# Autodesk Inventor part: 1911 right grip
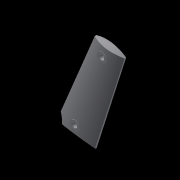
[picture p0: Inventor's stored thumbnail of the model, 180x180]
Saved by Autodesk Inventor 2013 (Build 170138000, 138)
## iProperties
Created: 2012-12
Part Number: 1911 right grip
Material: Generic
Document SubType Name: Modeling
Designer: John
Density: 1 g/cm^3
Author: John
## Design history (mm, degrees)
sketch "Sketch1"
  geometry: L1 (-53.04, -101.07)-(-35.834, -46.497) reference; L2 (-10.008, -33.299)-(0.762, -33.299); L3 (0.762, -9.83)-(-10.008, -9.83); L4 (0.762, -36.551)-(-22.268, -36.551) reference; L5 (15.748, -21.565)-(15.748, -19.304); L6 (67.564, -8.128)-(26.924, -8.128); L7 (-76.708, -32.918)-(-101.947, -93.849) reference; L8 (-101.947, -93.849)-(-53.04, -101.07) reference; L9 (67.564, -8.128)-(67.564, 5.867) reference; L10 (67.564, 5.867)-(9.144, 5.867) reference; L11 (9.144, 5.867)-(9.144, 11.43) reference; L12 (-81.119, 7.237)-(-80.862, 11.43); L13 (9.144, 11.43)-(-80.862, 11.43); L14 (-87.018, -8.028)-(-94.136, -5.079) reference; C1 r 2.553 at (0, 0) reference; C2 r 1.994 at (-95.123, -91.313) reference; C3 r 2 at (-75.514, 0.406) reference; C4 r 1.905 at (-85.547, -5.334) reference; C5 r 3.175 at (-30.302, -27.813); A1 r 11.735 centre (0.762, -21.565) between (0.762, -33.299) and (0.762, -9.83) reference; A2 r 14.986 centre (0.762, -21.565) between (0.762, -36.551) and (15.748, -21.565) reference; A3 r 11.735 centre (-10.008, -21.565) between (-10.008, -9.83) and (-10.008, -33.299) reference; A4 r 14.224 centre (-22.268, -50.775) between (-22.268, -36.551) and (-35.834, -46.497) reference; A5 r 11.176 centre (26.924, -19.304) between (26.924, -8.128) and (15.748, -19.304) reference; A6 r 8.763 centre (-89.865, 7.772) between (-88.554, -0.892) and (-81.119, 7.237) reference; A7 r 7.366 centre (-87.452, -8.175) between (-88.554, -0.892) and (-94.136, -5.079); A8 r 19.05 centre (-94.308, -25.628) between (-76.708, -32.918) and (-87.018, -8.028) reference; 3 further points
  constraints: 28 end point, 17 point on circle, 13 centre point, 13 tangent, 5 perpendicular, 2 coincident, 2 horizontal, 2 vertical, 1 midpoint, 1 parallel, 18 other
  dimensions: "d145" = 6.35 diameter of C5
extrude "Extrusion2" new body sketch "Sketch1" stored distance "d59" = 19.3548; taper "d60" = 0 deg
sketch "3D Sketch2"
sweep "Sweep2" sketch "3D Sketch2" dims "d62" = 0
sketch "Sketch4"
  geometry: L1 (-76.073, -16.93)-(-84.092, -1.85) reference; L2 (-74.409, -30.482)-(-81.214, -57.775) reference; L3 (-92.893, -13.174)-(-101.295, -13.174) reference; L4 (-77.94, -44.643)-(-90.574, -45.416); L5 (-90.574, -45.416)-(-82.294, -32.869); C1 r 1.905 at (-85.547, -5.334) reference; A1 r 19.05 centre (-92.893, -25.874) between (-74.409, -30.482) and (-76.073, -16.93) reference; A2 r 12.7 centre (-92.893, -25.874) between (-89.029, -13.776) and (-92.893, -13.174) reference; A3 r 35.814 centre (-88.437, -37.399) between (-84.092, -1.85) and (-98.411, -3.002) reference; A4 r 2.794 centre (-101.295, -10.38) between (-104.089, -10.38) and (-101.295, -13.174) reference; A5 r 2.794 centre (-101.295, -10.38) between (-104.087, -10.278) and (-101.295, -13.174); A6 r 7.874 centre (-96.219, -10.564) between (-98.411, -3.002) and (-104.087, -10.278) reference; A7 r 12.7 centre (-92.893, -25.874) between (-89.029, -13.776) and (-92.893, -13.174); A8 r 12.7 centre (-92.893, -25.874) between (-82.294, -32.869) and (-92.893, -13.174); 2 further points
  constraints: 18 point on circle, 10 end point, 9 centre point, 4 coincident, 2 concentric, 1 horizontal, 1 point on line, 1 tangent, 8 other
extrude "Extrusion3" join sketch "Sketch4" stored distance "d97" = 15.7226; taper "d98" = 0 deg
workplane "Work Plane1"
sketch "Sketch5"
  geometry: L1 (-7.861, 0)-(7.861, 0) reference; L2 (7.861, -12.018)-(7.861, 0) reference; L3 (-7.861, -12.018)-(7.861, -12.018) reference; L4 (-7.861, 0)-(-7.861, -12.018) reference; L5 (-3.937, 0)-(3.937, 0); L6 (-7.861, -12.018)-(-1.003, -12.018); L7 (0, 0)-(0, -8.629); A1 r 6.858 centre (-1.003, -6.199) between (-3.937, 0) and (-7.861, -6.199); A2 r 6.858 centre (1.003, -6.199) between (7.861, -6.199) and (3.937, 0); 1 further point
  constraints: 6 end point, 5 point on line, 4 point on circle, 2 centre point, 2 symmetric about line, 1 midpoint, 1 perpendicular, 2 other
extrude "Extrusion4" cut sketch "Sketch5" stored distance "d106" = 15.7226; taper "d107" = 0 deg
sketch "Sketch6"
  geometry: L1 (92.893, -13.174)-(101.295, -13.174) reference; L2 (94.719, -6.486)-(94.136, -5.079) reference; L3 (87.601, -9.435)-(94.719, -6.486) reference; L4 (101.295, -13.174)-(81.975, -13.174); A1 r 2.794 centre (101.295, -10.38) between (101.295, -13.174) and (104.087, -10.278) reference; A2 r 7.874 centre (96.219, -10.564) between (104.087, -10.278) and (98.411, -3.002) reference; A3 r 35.814 centre (88.437, -37.399) between (98.411, -3.002) and (90.909, -1.67) reference; A4 r 7.366 centre (87.452, -8.175) between (94.136, -5.079) and (90.909, -1.67) reference; 2 further points
  constraints: 2 end point, 1 collinear, 1 tangent, 2 other
extrude "Extrusion5" cut sketch "Sketch6" distance "d108" = 3.937; taper "d109" = 0 deg
mirror "Mirror1"
workplane "Work Plane2"
sweep "Sweep3" dims "d115" = 0
sweep "Sweep4" dims "d119" = 0
workplane "Work Plane3"
sweep "Sweep6" dims "d131" = 0
sketch "Sketch15"
  geometry: L1 (-20.851, -26.05)-(-20.851, -26.76) reference; L2 (-21.738, -21.901)-(-21.738, -26.76) reference; L3 (-25.508, -35.793)-(-26.989, -39.681); L4 (-26.989, -39.681)-(21.805, -39.681); L5 (21.805, -39.681)-(21.805, -10.457); L6 (21.805, -10.457)-(-11.471, -10.457); L7 (-11.471, -10.457)-(-21.738, -21.901); A1 r 15.328 centre (-22.268, -50.775) between (-24.079, -35.554) and (-25.508, -35.793) reference; A2 r 13.591 centre (-34.442, -26.76) between (-24.079, -35.554) and (-20.851, -26.76) reference; A3 r 11.735 centre (-10.008, -21.565) between (-21.738, -21.901) and (-20.851, -26.05) reference; A4 r 12.705 centre (-34.442, -26.76) between (-25.508, -35.793) and (-21.738, -26.76) reference; 1 further point
  constraints: 10 end point, 3 perpendicular
extrude "Extrusion6" cut sketch "Sketch15" stored distance "d132" = 37.338; taper "d133" = 0 deg
mirror "Mirror2"
workplane "Work Plane6"
sketch "Sketch21"
  geometry: L1 (0, 0)-(19.355, 0) reference; L2 (1.321, -3.607)-(1.321, 0); L3 (18.034, -3.607)-(18.034, 0); A1 r 10.389 centre (9.677, -3.607) between (0, -7.384) and (19.355, -7.384) reference; A2 r 8.357 centre (9.677, -3.607) between (1.321, -3.607) and (18.034, -3.607); 1 further point
  constraints: 4 end point, 2 point on circle, 2 point on line, 2 tangent, 1 centre point, 1 coincident, 1 parallel, 1 perpendicular
  dimensions: "d151" = 16.7132 diameter of A2
extrude "Extrusion7" cut sketch "Sketch21" stored distance "d152" = 37.338; taper "d153" = 0 deg
sketch "Sketch22"
  geometry: L1 (0, 5.563)-(19.355, 5.563) reference; L2 (0, 0)-(1.321, 0) reference; L3 (1.702, 0)-(1.702, 3.023); L4 (0, 3.023)-(1.702, 3.023); L5 (1.702, 0)-(0, 0); L6 (9.677, -3.607)-(9.677, 2.087); L7 (19.355, 3.023)-(17.653, 3.023); L8 (17.653, 0)-(17.653, 3.023); L9 (17.653, 0)-(19.355, 0); L10 (0, 3.023)-(0, 0); L11 (19.355, 3.023)-(19.355, 0); A1 r 8.357 centre (9.677, -3.607) between (1.321, -3.607) and (18.034, -3.607) reference; 1 further point
  constraints: 18 end point, 4 perpendicular, 3 symmetric about line, 1 collinear, 1 parallel
  dimensions: "d155" = 2.54 distance of L1.start L4.start
extrude "Extrusion8" cut sketch "Sketch22" stored distance "d156" = 37.338; taper "d157" = 0 deg
sweep "Sweep7" dims "d159" = 0
sketch "Sketch26"
  geometry: L1 (-94.719, -6.486)-(-94.136, -5.079); L2 (-87.601, -9.435)-(-94.719, -6.486); L3 (-87.601, -9.435)-(-94.579, -6.544) reference; L4 (-89.65, -13.174)-(-81.975, -13.174) reference; L5 (-92.893, -12.766)-(-102.748, -12.766) reference; L6 (-94.371, -4.976)-(-96.086, -9.116) reference; L7 (-96.086, -9.116)-(-95.709, -9.272) reference; L8 (-104.087, -10.278)-(-87.601, -9.435); A1 r 7.874 centre (-96.219, -10.564) between (-98.411, -3.002) and (-104.087, -10.278); A2 r 35.814 centre (-88.437, -37.399) between (-90.909, -1.67) and (-98.411, -3.002); A3 r 7.366 centre (-87.452, -8.175) between (-90.909, -1.67) and (-94.136, -5.079); A4 r 13.108 centre (-92.893, -25.874) between (-89.65, -13.174) and (-92.893, -12.766) reference; A5 r 2.794 centre (-101.295, -10.38) between (-104.087, -10.278) and (-102.748, -12.766) reference; A6 r 7.874 centre (-96.219, -10.564) between (-98.411, -3.002) and (-104.087, -10.278) reference; A7 r 35.814 centre (-88.437, -37.399) between (-91.5, -1.716) and (-98.411, -3.002) reference; A8 r 7.622 centre (-87.452, -8.175) between (-91.5, -1.716) and (-94.371, -4.976) reference; 1 further point
  constraints: 6 end point, 6 point on circle, 3 centre point, 2 other
extrude "Extrusion9" join sketch "Sketch26" stored distance "d160" = 7.8486; taper "d161" = 0 deg
sketch "Sketch27"
  geometry: L1 (0, 0)-(-41.219, -130.729); L2 (0, 0)-(137.073, 0); L3 (-55.804, 11.43)-(-98.449, -123.824); L4 (-79.932, 11.43)-(9.144, 11.43) reference; L5 (-89.574, -95.676)-(-61.783, -99.779); L6 (-61.783, -99.779)-(-26.719, 11.43); C1 r 1.994 at (-95.123, -91.313) reference
  constraints: 10 end point, 3 point on line, 1 equal length, 1 horizontal, 1 parallel
  dimensions: "d162" = 107.5 deg angle of L1 L2; "d165" = 28.0924 distance of L5.start L5.end
extrude "Extrusion10" cut sketch "Sketch27" stored distance "d166" = 13.9954; taper "d167" = 0 deg
workplane "Work Plane7"
sketch "Sketch28"
  geometry: C1 r 6.998 at (0, 0); 1 further point
  constraints: 1 centre point
  dimensions: "d169" = 13.9954 diameter of C1
extrude "Extrusion11" cut sketch "Sketch28" stored distance "d170" = 22.5171; taper "d171" = 0 deg
workplane "Work Plane8"
sketch "Sketch30"
  geometry: L1 (-10.008, -9.83)-(0.762, -9.83) reference; L2 (0.762, -33.299)-(-10.008, -33.299) reference; A1 r 11.735 centre (-10.008, -21.565) between (-10.008, -9.83) and (-21.742, -21.565) reference; A2 r 11.735 centre (0.762, -21.565) between (0.762, -33.299) and (1.099, -9.835) reference; A3 r 11.735 centre (-10.008, -21.565) between (-21.738, -21.901) and (-10.008, -33.299) reference; 1 further point
  constraints: 2 other
sweep "Sweep8" sketch "Sketch30" dims "d173" = 0
sketch "Sketch31"
  geometry: L1 (31.241, 6.452)-(41.564, 6.452); L2 (31.241, 6.452)-(31.241, -6.452); L3 (31.241, -6.452)-(41.564, -6.452); L4 (41.564, -6.452)-(41.564, 6.452); 7 further points; 2 other entities
  constraints: 8 end point, 2 horizontal, 1 perpendicular, 1 vertical, 2 other
  dimensions: "d174" = 6.4516 distance of point (31.241, 0) L1.start; "d175" = 12.9032 distance of L1.start L2.end
extrude "Extrusion12" cut sketch "Sketch31" distance "d176" = 2.159; taper "d177" = 0 deg
sketch "Sketch32"
  geometry: C1 r 2.54 at (-76.657, -84.049); C2 r 2.54 at (-49.2, -10.947)
  constraints: 2 centre point
  dimensions: "d180" = 5.08 diameter of C1; "d185" = 5.08 diameter of C2
extrude "Extrusion13" cut sketch "Sketch32" stored distance "d181" = 2.159; taper "d182" = 0 deg
sketch "Sketch33"
  geometry: L1 (-55.804, 11.43)-(-89.574, -95.676) reference; L2 (-82.294, -32.869)-(-90.574, -45.416) reference; L3 (-85.446, -45.102)-(-90.059, -45.384) reference; L4 (-90.574, -45.416)-(-90.059, -45.384) reference; L5 (-89.328, -43.527)-(-86.814, -45.186); 1 further point
  constraints: 2 end point, 2 point on line, 1 perpendicular
extrude "Extrusion14" cut sketch "Sketch33" distance "d186" = 25.4; taper "d187" = 0 deg
sketch "Sketch34"
  geometry: L1 (59.664, -100.092)-(101.947, -93.849) reference; L2 (92.046, -94.569)-(60.876, -99.275) reference; L3 (31.159, -5.307)-(60.937, -99.266) reference; L4 (61.169, -0.636)-(95.891, -84.128); C1 r 2.54 at (76.657, -84.049) reference; C2 r 2.54 at (49.2, -10.947) reference; A1 r 8.636 centre (100.167, -91.631) between (95.891, -84.128) and (92.334, -95.268); A2 r 34.544 centre (50.936, -33.629) between (61.169, -0.636) and (31.159, -5.307)
  constraints: 6 end point, 5 point on circle, 2 centre point, 2 point on line, 3 other
extrude "Extrusion15" join sketch "Sketch34" distance "d209" = 6.477; taper "d210" = 0 deg
workplane "Work Plane9"
workplane "Work Plane12"
workplane "Work Plane13"
loft "Loft1" dims "d219" = 0, "d220" = 90 deg, "d221" = 0, "d222" = 90 deg
workplane "Work Plane14"
sketch "Sketch39"
  geometry: L1 (0, 0)-(1.524, 0) reference; L2 (1.524, 0)-(9.15, -7.626); L3 (1.524, 0)-(12.309, 0); L4 (9.15, -7.626)-(9.15, 0); L5 (9.15, 0)-(1.524, 0); 1 further point
  constraints: 8 end point, 2 perpendicular, 1 equal length, 1 horizontal, 1 point on line
  dimensions: "d224" = 45 deg angle of L2 L3
extrude "Extrusion16" cut sketch "Sketch39" distance "d225" = 44.82993; taper "d226" = 0 deg
sketch "3D Sketch3"
sweep "Sweep9" sketch "3D Sketch3" dims "d228" = 0
mirror "Mirror3"
mirror "Mirror4"
sketch "Sketch41"
  geometry: L1 (-10.008, -32.408)-(0.762, -32.408) reference; L2 (-10.008, -10.721)-(0.762, -10.721) reference; L3 (-10.008, -10.721)-(-17.523, -10.721); L4 (-10.008, -32.408)-(-17.523, -32.408); A1 r 12.7 centre (-2.998, -21.565) between (-9.608, -10.721) and (-9.608, -32.408); A2 r 13.193 centre (-10.008, -21.565) between (-17.523, -10.721) and (-17.523, -32.408); 2 further points
  constraints: 4 end point, 4 point on circle, 2 centre point, 2 point on line, 1 coincident, 1 collinear, 1 parallel
extrude "Extrusion17" join sketch "Sketch41" stored distance "d230" = 5.7404; taper "d231" = 0 deg
sketch "Sketch43"
  geometry: A1 r 12.7 centre (-2.998, -21.565) between (-9.608, -10.721) and (-9.608, -32.408) reference; 1 further point
sweep "Sweep10" sketch "Sketch43" dims "d233" = 0
sketch "Sketch44"
  geometry: L1 (9.144, 8.89)-(9.144, 11.43) reference; L2 (9.144, 11.43)-(-79.932, 11.43) reference; L3 (9.144, 11.43)-(9.144, 11.176); L4 (9.144, 11.176)-(-89.177, 11.176); L5 (-89.177, 11.176)-(-89.177, 11.43); L6 (-89.177, 11.43)-(-79.932, 11.43); 1 further point
  constraints: 8 end point, 2 parallel, 2 point on line, 1 perpendicular
  dimensions: "d234" = 0.254 distance of L1.end L3.end
extrude "Extrusion18" cut sketch "Sketch44" stored distance "d235" = 5.7404; taper "d236" = 0 deg
sketch "Sketch45"
  geometry: L1 (18.034, 8.915)-(-1.321, 8.915) reference; L2 (-1.321, 6.629)-(-1.321, 8.915) reference; L3 (-1.321, 6.629)-(0.381, 6.629) reference; L4 (16.332, 6.629)-(18.034, 6.629) reference; L5 (18.034, 8.915)-(18.034, 6.629) reference; L6 (18.034, 6.629)-(17.78, 6.629); L7 (17.78, 6.629)-(17.78, 8.915); L8 (-1.321, 6.629)-(-1.067, 6.629); L9 (-1.067, 6.629)-(-1.067, 8.915); 1 further point
  constraints: 8 end point, 4 point on line, 2 perpendicular
  dimensions: "d237" = 0.254 distance of L4.end L6.end; "d238" = 0.254 distance of L2.start L8.end
extrude "Extrusion19" cut sketch "Sketch45" stored distance "d239" = 25.4; taper "d240" = 0 deg
sketch "Sketch47"
  geometry: L1 (-84.404, 0.406)-(-84.404, 18.681); L2 (-84.404, 18.681)-(-73.514, 18.681); L3 (-73.514, 9.068)-(-73.514, 18.681); C1 r 2 at (-75.514, 0.406) reference; A1 r 8.89 centre (-75.514, 0.406) between (-84.404, 0.406) and (-66.624, 0.406); A2 r 8.89 centre (-75.514, 0.406) between (-84.404, 0.406) and (-73.514, 9.068); 1 further point
  constraints: 6 end point, 5 point on circle, 2 centre point, 2 coincident, 2 perpendicular, 2 tangent, 1 vertical
extrude "Extrusion21" cut sketch "Sketch47" stored distance "d245" = 8.001; taper "d246" = 0 deg
sketch "Sketch51"
  geometry: C1 r 2.54 at (49.2, -10.947) reference; C2 r 2.54 at (76.657, -84.049) reference; C3 r 4.826 at (49.2, -10.947); C4 r 4.826 at (76.657, -84.049); 1 further point
  constraints: 2 centre point, 2 coincident
  dimensions: "d251" = 9.652 diameter of C3; "d252" = 9.652 diameter of C4
extrude "Extrusion22" join sketch "Sketch51" distance "d253" = 9.398; taper "d254" = 0 deg
mirror "Mirror5"
sketch "Sketch52"
  geometry: L1 (17.78, 8.915)-(-1.067, 8.915) reference; L2 (12.992, 3.321)-(12.992, 8.915); L3 (3.721, 3.321)-(3.721, 8.915); L4 (3.721, 8.915)-(12.992, 8.915); A1 r 8.357 centre (8.357, 0) between (0, 0) and (16.713, 0) reference; A2 r 5.702 centre (8.357, 0) between (3.721, 3.321) and (12.992, 3.321); 1 further point
  constraints: 6 end point, 2 point on circle, 2 point on line, 1 centre point, 1 coincident, 1 collinear, 1 perpendicular
extrude "Extrusion23" cut sketch "Sketch52" distance "d258" = 20.1168; taper "d259" = 0 deg
sketch "Sketch53"
  geometry: L1 (10.3, -7.696)-(10.3, -5.361); L2 (10.3, -7.696)-(6.414, -7.696); L3 (6.414, -7.696)-(6.414, -5.361); A1 r 5.702 centre (8.357, 0) between (3.721, 3.321) and (12.992, 3.321) reference; 1 further point
  constraints: 6 end point, 2 perpendicular, 2 point on circle
extrude "Extrusion24" cut sketch "Sketch53" distance "d263" = 13.7668; taper "d264" = 0 deg
sketch "Sketch54"
  geometry: L1 (12.992, 8.915)-(12.992, 3.321) reference; L2 (3.721, 8.915)-(12.992, 8.915); A1 r 8.839 centre (8.357, 16.442) between (3.721, 8.915) and (12.992, 8.915); 1 further point
  constraints: 2 end point, 2 point on circle, 1 centre point, 1 perpendicular
extrude "Extrusion25" cut sketch "Sketch54" distance "d266" = 34.925; taper "d267" = 0 deg
sketch "Sketch55"
  geometry: L1 (67.564, 5.867)-(-80.363, 5.867) reference; L2 (-20.469, -6.245)-(-10.008, -6.245); L3 (-20.469, -24.235)-(0, -24.235); A1 r 15.32 centre (-10.008, -21.565) between (-10.008, -6.245) and (-25.327, -21.565) reference; A2 r 8.995 centre (-20.469, -15.24) between (-20.469, -6.245) and (-20.469, -24.235) reference
  constraints: 4 end point, 3 tangent, 2 parallel, 2 point on circle, 1 centre point, 2 other
workplane "Work Plane17"
sketch "Sketch56"
  geometry: L1 (-8.995, 0)-(0, 0) reference; L2 (0, 0)-(0, 1.901); A1 r 22.225 centre (0, -20.324) between (0, 1.901) and (-8.995, 0); 1 further point
  constraints: 2 end point, 2 point on circle, 1 centre point
sweep "Sweep11" sketch "Sketch56" dims "d270" = 0
mirror "Mirror6"
sketch "Sketch57"
  geometry: L1 (-155.378, 38.543)-(119.635, 38.543); L2 (119.635, 38.543)-(119.635, -104.796); L3 (119.635, -104.796)-(-155.378, -104.796); L4 (-155.378, -104.796)-(-155.378, 38.543)
  constraints: 8 end point, 2 parallel, 1 horizontal, 1 perpendicular
extrude "Extrusion26" cut sketch "Sketch57" stored distance "d271" = 25.4; taper "d272" = 0 deg
body "Solid2"
sketch "Sketch3"
  geometry: L1 (0, 19.355)-(0, 0) reference; L2 (-49.437, 19.355)-(0, 19.355) reference; L3 (-49.437, 19.355)-(-49.437, 0) reference; L4 (0, 0)-(-49.437, 0) reference; A1 r 13.462 centre (-40.079, 9.677) between (-49.437, 19.355) and (-49.437, 0); 1 further point
  constraints: 2 point on circle, 1 centre point, 1 end point, 1 point on line
node "Projected Loop1"
sketch "Sketch7"
  geometry: L1 (-7.874, -1.702)-(-7.874, 0.419); L2 (-7.874, 0.419)-(7.861, 0.419); L3 (7.861, 0.419)-(7.861, -1.702); A1 r 19.037 centre (-0.006, -19.037) between (7.861, -1.702) and (-7.874, -1.702); 1 further point
  constraints: 6 end point, 2 point on circle, 1 centre point, 1 parallel, 1 perpendicular, 1 vertical
sketch "Sketch8"
  geometry: L1 (-86.303, -38.944)-(-82.294, -32.869) reference; L2 (-86.303, -38.944)-(-90.574, -45.416) reference; L3 (-92.893, -13.174)-(-101.295, -13.174) reference; L4 (-101.295, -13.174)-(-113.16, -13.174); A1 r 12.7 centre (-92.893, -25.874) between (-82.294, -32.869) and (-92.893, -13.174) reference; 1 further point
  constraints: 2 end point
sketch "Sketch10"
  geometry: L1 (-53.04, -101.07)-(-35.834, -46.497) reference; L2 (-22.268, -36.551)-(0.762, -36.551) reference; L3 (15.748, -21.565)-(15.748, -19.304) reference; L4 (26.924, -8.128)-(67.564, -8.128) reference; L5 (-53.04, -101.07)-(-58.066, -117.009); A1 r 14.224 centre (-22.268, -50.775) between (-22.268, -36.551) and (-35.834, -46.497) reference; A2 r 14.986 centre (0.762, -21.565) between (0.762, -36.551) and (15.748, -21.565) reference; A3 r 11.176 centre (26.924, -19.304) between (26.924, -8.128) and (15.748, -19.304) reference; 1 further point
  constraints: 2 end point, 1 collinear
sketch "Sketch11"
  geometry: L1 (0, 6.611)-(0, -0.578); L2 (0, -0.578)-(19.807, -0.578); L3 (19.355, 6.611)-(19.355, -0.578); A1 r 10.389 centre (9.677, 10.389) between (0, 6.611) and (19.355, 6.611); 1 further point
  constraints: 6 end point, 2 perpendicular, 2 point on circle, 1 centre point, 1 point on line, 1 vertical
sketch "Sketch12"
  geometry: L1 (0, 0)-(19.355, 0) reference; L2 (0, -15.697)-(19.355, -15.697) reference; L3 (0, -15.697)-(19.355, -15.697) reference; L4 (0, -12.112)-(0, -16.588); L5 (19.355, -16.588)-(19.355, -12.112); L6 (5.017, -16.588)-(5.017, -15.702); L7 (0, -16.588)-(5.017, -16.588); L8 (14.338, -16.588)-(14.338, -15.702); L9 (14.338, -16.588)-(19.355, -16.588); A1 r 12.7 centre (9.677, -3.888) between (0, -12.112) and (19.355, -12.112)
  constraints: 12 end point, 4 perpendicular, 4 point on circle, 1 centre point, 1 parallel
sketch "Sketch13"
  geometry: L1 (-10.008, -9.83)-(0.762, -9.83) reference; L2 (-21.742, -21.565)-(-21.742, -26.76); L3 (0.762, -9.83)-(27.888, -9.83); A1 r 11.735 centre (-10.008, -21.565) between (-10.008, -9.83) and (-21.742, -21.565); A2 r 14.224 centre (-22.268, -50.775) between (-28.7, -38.088) and (-35.834, -46.497); A3 r 12.7 centre (-34.442, -26.76) between (-28.7, -38.088) and (-21.742, -26.76); 3 further points
  constraints: 7 point on circle, 5 end point, 3 centre point, 2 perpendicular, 2 tangent, 1 coincident
node "Projected Loop2"
node "Projected Loop3"
sketch "Sketch23"
  geometry: L1 (0, 0)-(0, 19.355) reference; L2 (90.006, 0)-(0, 0) reference; L3 (0, 19.355)-(90.006, 19.355) reference; L4 (0.93, 0)-(-0.257, 0); L5 (-0.257, 0)-(-0.257, 19.355); L6 (-0.257, 19.355)-(0.93, 19.355); A1 r 50.8 centre (50.8, 9.677) between (0.93, 19.355) and (0.93, 0); 1 further point
  constraints: 6 end point, 2 parallel, 2 point on circle, 2 point on line, 1 centre point, 1 collinear
sketch "Sketch24"
  geometry: L1 (-81.017, 8.89)-(-80.862, 11.43) reference; L2 (-81.017, 8.89)-(-81.119, 7.237) reference; L3 (-94.719, -6.486)-(-94.136, -5.079) reference; L4 (-94.719, -6.486)-(-95.849, -9.214); A1 r 8.763 centre (-89.865, 7.772) between (-81.312, 5.867) and (-81.119, 7.237) reference; A2 r 8.763 centre (-89.865, 7.772) between (-88.554, -0.892) and (-81.312, 5.867) reference; A3 r 7.366 centre (-87.452, -8.175) between (-88.554, -0.892) and (-94.136, -5.079) reference; 1 further point
  constraints: 2 end point, 1 collinear
node "Projected Loop4"
sketch "Sketch29"
  geometry: L1 (-11.735, 0.012)-(-11.735, -9.334) reference; A1 r 12.7 centre (-23.544, -4.661) between (-11.735, -9.334) and (-11.735, 0.012); 1 further point
  constraints: 2 end point, 2 point on circle, 1 centre point
sketch "Sketch36"
  geometry: L1 (0, -38.046)-(1.524, -38.046); L2 (1.524, -38.046)-(1.524, 0); L3 (8.105, 0)-(8.105, -38.046); L4 (1.524, -38.046)-(1.524, -41.858); L5 (1.524, -41.858)-(8.105, -41.858); L6 (8.105, -41.858)-(8.105, -38.046); L7 (1.524, 0)-(1.524, 3.852); L8 (1.524, 3.852)-(8.105, 3.852); L9 (8.105, 3.852)-(8.105, 0); A1 r 39.007 centre (-32.53, -19.023) between (1.524, -38.046) and (1.524, 0); 1 further point
  constraints: 18 end point, 4 parallel, 2 perpendicular, 2 point on circle, 1 centre point
sketch "Sketch38"
  geometry: L1 (0, 0)-(1.524, 0); L2 (1.524, 0)-(1.524, -29.737); L3 (8.43, 0)-(8.43, -35.358); L4 (1.524, 0)-(1.524, 5.541); L5 (1.524, 5.541)-(8.43, 5.541); L6 (8.43, 5.541)-(8.43, 0); L7 (1.524, -29.737)-(1.524, -35.358); L8 (1.524, -35.358)-(8.43, -35.358); A1 r 24.793 centre (-18.316, -14.868) between (1.524, -29.737) and (1.524, 0); 1 further point
  constraints: 16 end point, 2 point on circle, 1 centre point, 1 parallel, 1 perpendicular
sketch "Sketch40"
  geometry: L1 (1.524, 0)-(1.524, 73.924) reference; L2 (0, 0)-(0, 98.565) reference; L3 (0, 98.565)-(0, 85.865); L4 (0, 98.565)-(0, 103.317); L5 (0, 103.317)-(11.176, 103.317); L6 (11.176, 103.317)-(11.176, 91.897); A1 r 12.7 centre (0, 85.865) between (11.176, 91.897) and (0, 98.565); A2 r 12.7 centre (0, 85.865) between (0, 73.165) and (1.524, 73.257); 1 further point
  constraints: 8 end point, 4 point on circle, 3 point on line, 2 centre point, 1 coincident, 1 parallel, 1 perpendicular
sketch "Sketch42"
  geometry: L1 (-6.649, -1.791)-(-5.613, -1.791); L2 (-5.613, -1.791)-(-5.613, -7.531); L3 (-5.613, -7.531)-(-6.649, -7.531); A1 r 4.775 centre (-10.465, -4.661) between (-6.649, -7.531) and (-6.649, -1.791); 1 further point
  constraints: 6 end point, 2 point on circle, 1 centre point
other parameters: "d99" = 90 deg, "d105" = 13.716, "d110" = 90 deg, "d120" = -39.6875, "d168" = 90 deg, "d202" = 17.272, "d208" = 69.088, "d223" = 90 deg
